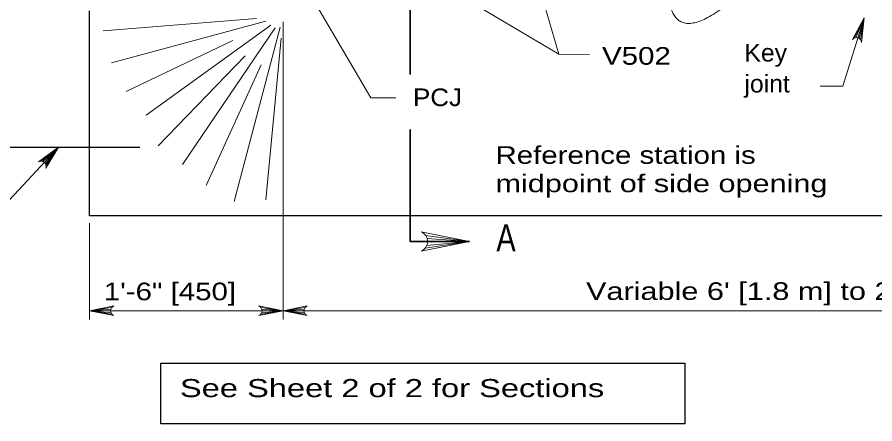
# Model space of a CAD drawing. Extents: x 339.1 to 373.1, y 1412.7 to 1456.7.
# Drawn here: x 343.47 to 351.06, y 1445.91 to 1449.51 of the extents above; entities that cross this region are included whole.
import ezdxf

# ---------------------------------------------------------------- set-up
doc = ezdxf.new("R2010")
doc.units = 0
doc.header["$LTSCALE"] = 0.062
doc.layers.add('1', color=7, linetype='Continuous', lineweight=13)

msp = doc.modelspace()

# ---------------------------------------------------------------- linework, layer by layer
at = {"layer": '1', "lineweight": 35}
for p, q in [((346.95083, 1450.14908), (346.95083, 1449.00067)), ((346.95083, 1448.51317), (346.95083, 1447.98658)), ((346.95083, 1448.08133), (346.95083, 1447.70842)), ((346.95083, 1447.87375), (346.95083, 1447.78717)), ((346.95083, 1447.70842), (346.95083, 1447.52275)), ((346.95083, 1447.52275), (347.47433, 1447.52275))]:
    msp.add_line(p, q, dxfattribs=at)
at = {"layer": '1'}
for p, q in [((347.0465, 1449.903), (348.2655, 1449.18067)), ((348.06925, 1449.85725), (348.2655, 1449.18067)), ((345.58792, 1449.4955), (344.23008, 1449.38758)), ((345.67017, 1449.47283), (344.30317, 1449.104)), ((345.82367, 1449.46742), (345.82367, 1446.83117)), ((350.88258, 1449.32325), (350.96875, 1449.502)), ((350.89683, 1449.32667), (350.96875, 1449.502)), ((350.9145, 1449.32483), (350.96875, 1449.502)), ((350.927, 1449.31892), (350.96875, 1449.502)), ((350.93792, 1449.30867), (350.96875, 1449.502)), ((345.7165, 1449.43658), (344.61233, 1448.63925)), ((344.93433, 1448.20358), (345.75492, 1449.41233)), ((345.38942, 1447.87725), (345.799, 1449.41942)), ((345.3775, 1449.30092), (344.43533, 1448.85067)), ((345.671, 1447.89083), (345.80617, 1449.32358)), ((345.48708, 1449.16608), (344.71675, 1448.37017)), ((348.2655, 1449.18067), (348.53675, 1449.17642)), ((345.14392, 1448.018), (345.62892, 1449.08483)), ((343.68067, 1448.23342), (343.83583, 1448.35708)), ((343.69492, 1448.23033), (343.83583, 1448.35708)), ((343.71, 1448.221), (343.83583, 1448.35708)), ((343.71867, 1448.21025), (343.83583, 1448.35708)), ((343.72408, 1448.19633), (343.83583, 1448.35708)), ((344.11025, 1447.685), (344.11025, 1446.83117)), ((347.08658, 1447.577), (347.47433, 1447.52275)), ((347.09975, 1447.55017), (347.47433, 1447.52275)), ((347.082, 1447.46275), (347.47433, 1447.52275)), ((347.09683, 1447.48792), (347.47433, 1447.52275)), ((347.10375, 1447.52275), (347.47433, 1447.52275)), ((344.30417, 1446.937), (344.11025, 1446.90983)), ((344.29758, 1446.92358), (344.11025, 1446.90983)), ((345.82367, 1446.90983), (344.11025, 1446.90983)), ((344.29558, 1446.90983), (344.11025, 1446.90983)), ((344.299, 1446.89242), (344.11025, 1446.90983)), ((344.3065, 1446.87983), (344.11025, 1446.90983)), ((345.6275, 1446.87983), (345.82367, 1446.90983)), ((345.62975, 1446.937), (345.82367, 1446.90983)), ((345.63492, 1446.89242), (345.82367, 1446.90983)), ((345.63633, 1446.92358), (345.82367, 1446.90983)), ((345.63833, 1446.90983), (345.82367, 1446.90983)), ((346.0175, 1446.937), (345.82367, 1446.90983)), ((346.011, 1446.92358), (345.82367, 1446.90983)), ((346.009, 1446.90983), (345.82367, 1446.90983)), ((346.01242, 1446.89242), (345.82367, 1446.90983)), ((346.01983, 1446.87983), (345.82367, 1446.90983))]:
    msp.add_line(p, q, dxfattribs=at)
at = {"layer": '1', "lineweight": 25}
for p, q in [((344.11025, 1447.75067), (344.11025, 1449.56467)), ((344.55492, 1448.35533), (342.06367, 1448.35533)), ((348.158, 1447.75067), (344.11025, 1447.75067)), ((353.90383, 1447.75067), (348.158, 1447.75067))]:
    msp.add_line(p, q, dxfattribs=at)
at = {"layer": '1'}
for points in [[(345.82367, 1450.11967), (346.6005, 1448.7935), (346.82142, 1448.7935)], [(350.96875, 1449.502), (350.78, 1448.89625), (350.57933, 1448.89625)], [(350.86508, 1449.30975), (350.96875, 1449.502), (350.947, 1449.28467)], [(343.83583, 1448.35708), (343.32525, 1447.80808), (343.08417, 1447.80808)], [(343.659, 1448.22892), (343.83583, 1448.35708), (343.72183, 1448.17075)], [(347.046, 1447.43708), (347.47433, 1447.52275), (347.046, 1447.60842)], [(344.32442, 1446.867), (344.11025, 1446.90983), (344.32442, 1446.95267)], [(345.6095, 1446.867), (345.82367, 1446.90983), (345.6095, 1446.95267)], [(346.03783, 1446.867), (345.82367, 1446.90983), (346.03783, 1446.95267)], [(357.15083, 1446.90983), (352.38625, 1446.90983), (345.82367, 1446.90983)]]:
    msp.add_lwpolyline(points, dxfattribs=at)
at = {"layer": '1', "lineweight": 25}
msp.add_lwpolyline([(344.74075, 1446.4465), (349.38183, 1446.4465), (349.38183, 1445.90867), (344.74075, 1445.90867)], close=True, dxfattribs=at)
at = {"layer": '1'}
for centre, radius, start, end in [((350.901, 1449.28069), 0.04623, 5.0513, 140.87743), ((343.6787, 1448.18714), 0.04623, 339.31062, 115.13674), ((347.01144, 1447.52282), 0.09245, 292.08605, 67.91218), ((344.34175, 1446.9099), 0.04623, 112.08782, 247.91395), ((345.59217, 1446.9099), 0.04623, 292.08605, 67.91218), ((346.05511, 1446.9099), 0.04623, 112.08782, 247.91395)]:
    msp.add_arc(centre, radius, start, end, dxfattribs=at)
msp.add_open_spline([(349.235, 1449.86692), (349.20283, 1449.15325), (349.81833, 1449.669)], degree=2, dxfattribs=at)

# ---------------------------------------------------------------- texts
for s, height, width, p in [('V502', 0.156, 1.25, (348.6485, 1449.08708)), ('Key', 0.156, 1.05, (349.9095, 1449.11558)), ('joint', 0.156, 1.05, (349.9095, 1448.84158)), ('PCJ', 0.156, 1.1, (346.97475, 1448.72083)), ('Reference station is', 0.156, 1.25, (347.70492, 1448.20992)), ('midpoint of side opening', 0.156, 1.3, (347.70492, 1447.95875)), ('A', 0.24, 0.8, (347.71258, 1447.43575)), ('1\'-6" [450]', 0.156, 1.25, (344.23608, 1447.0025)), ("Variable 6' [1.8 m] to 20' [6.0 m]", 0.156, 1.3, (348.50683, 1447.00542)), ('See Sheet 2 of 2 for Sections', 0.16, 1.35, (344.9105, 1446.145))]:
    msp.add_text(s, height=height, dxfattribs=dict(at, width=width)).set_placement(p)

doc.saveas('drawing.dxf')
